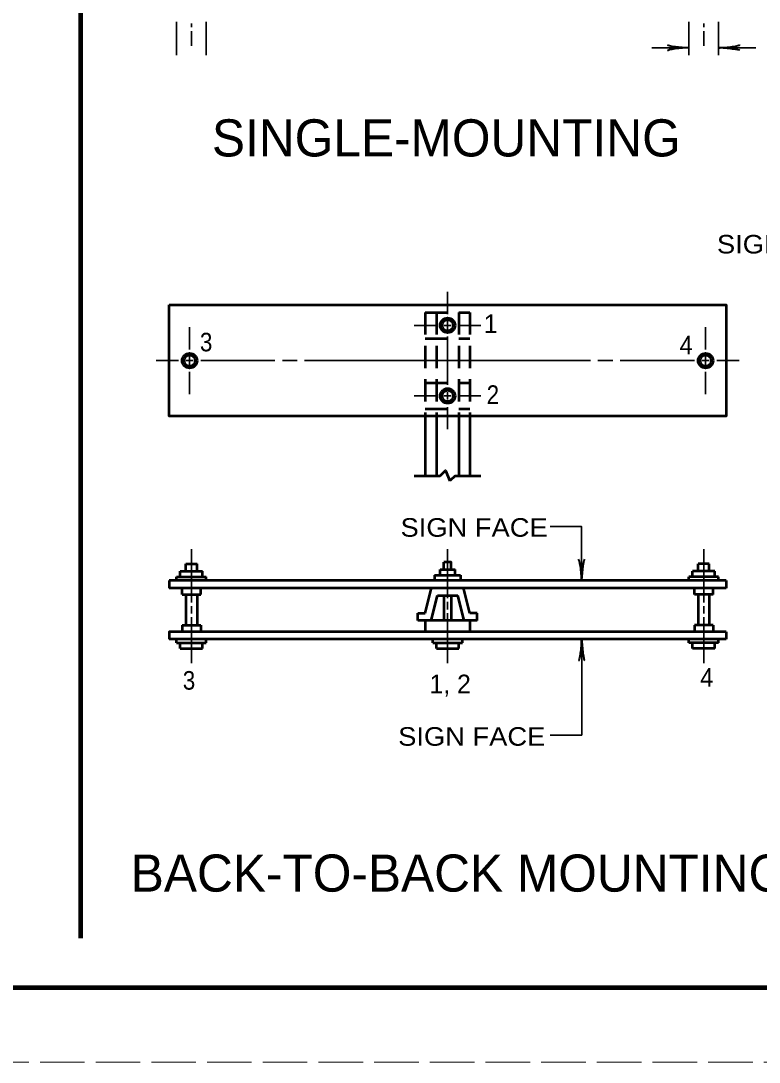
# Model space of a CAD drawing. Extents: x -41 to 639, y -374 to 66.
# Drawn here: x 278.2 to 377.7, y -374.1 to -233.9 of the extents above; entities that cross this region are included whole.
import ezdxf

# ---------------------------------------------------------------- set-up
doc = ezdxf.new("R2010")
doc.units = 0
doc.linetypes.add('LONG_DASHED', pattern=[7.5, 6, -1.5])
doc.linetypes.add('MEDIUM_DASHED', pattern=[4.5, 3, -1.5])
doc.layers.add('1', color=7, linetype='Continuous', lineweight=53)
doc.layers.add('61', color=7, linetype='Continuous', lineweight=35)

msp = doc.modelspace()

# ---------------------------------------------------------------- linework, layer by layer
at = {"layer": '1', "lineweight": 200}
msp.add_line((286.229, -93.651), (286.229, -357.39), dxfattribs=at)
at = {"layer": '1', "lineweight": 35}
for p, q in [((299.192, -238.508), (299.192, -234.008)), ((303.192, -238.508), (303.192, -234.008)), ((368.192, -238.508), (368.192, -234.008)), ((372.192, -238.508), (372.192, -234.008)), ((301.192, -234.758), (301.192, -234.258)), ((301.192, -235.258), (301.192, -237.258)), ((370.192, -234.758), (370.192, -234.258)), ((370.192, -235.258), (370.192, -237.258)), ((363.192, -237.508), (368.192, -237.508)), ((372.192, -237.508), (377.192, -237.508)), ((335.692, -273.386), (335.692, -270.386)), ((335.692, -274.386), (335.692, -275.386)), ((300.942, -278.136), (300.942, -275.136)), ((334.192, -274.886), (331.192, -274.886)), ((336.192, -274.886), (335.192, -274.886)), ((337.192, -274.886), (340.192, -274.886)), ((370.442, -278.136), (370.442, -275.136)), ((335.692, -276.386), (335.692, -279.636)), ((299.442, -279.636), (296.442, -279.636)), ((300.442, -279.636), (301.442, -279.636)), ((300.942, -279.136), (300.942, -280.136)), ((302.442, -279.636), (312.442, -279.636)), ((313.442, -279.636), (315.442, -279.636)), ((316.442, -279.636), (335.692, -279.636)), ((354.942, -279.636), (335.692, -279.636)), ((335.692, -282.886), (335.692, -279.636)), ((357.942, -279.636), (355.942, -279.636)), ((368.942, -279.636), (358.942, -279.636)), ((370.942, -279.636), (369.942, -279.636)), ((370.442, -279.136), (370.442, -280.136)), ((371.942, -279.636), (374.942, -279.636)), ((300.942, -281.136), (300.942, -284.136)), ((370.442, -281.136), (370.442, -284.136)), ((334.192, -284.386), (331.192, -284.386)), ((336.192, -284.386), (335.192, -284.386)), ((335.692, -284.886), (335.692, -283.886)), ((337.192, -284.386), (340.192, -284.386)), ((335.692, -285.886), (335.692, -288.886)), ((301.192, -305.005), (301.192, -312.195)), ((335.692, -311.636), (335.692, -305.005)), ((370.192, -305.005), (370.192, -312.195)), ((335.692, -313.136), (335.692, -312.136)), ((301.192, -312.695), (301.192, -313.695)), ((335.692, -320.386), (335.692, -313.636)), ((370.192, -312.695), (370.192, -313.695)), ((301.192, -314.195), (301.192, -320.386)), ((370.192, -314.195), (370.192, -320.386)), ((353.757, -317.158), (353.757, -330.06)), ((353.757, -330.06), (349.52, -330.06))]:
    msp.add_line(p, q, dxfattribs=at)
at = {"layer": '1', "linetype": 'MEDIUM_DASHED'}
for p, q in [((332.692, -273.136), (338.692, -273.136)), ((332.692, -273.136), (332.692, -287.136)), ((334.192, -273.136), (334.192, -287.136)), ((337.192, -273.136), (337.192, -287.136)), ((338.692, -273.136), (338.692, -287.136)), ((332.692, -276.636), (338.692, -276.636)), ((332.692, -282.636), (338.692, -282.636)), ((332.692, -286.136), (338.692, -286.136))]:
    msp.add_line(p, q, dxfattribs=at)
at = {"layer": '1'}
for p, q in [((332.692, -287.136), (332.692, -295.136)), ((334.192, -287.136), (334.192, -295.136)), ((337.192, -287.136), (337.192, -295.136)), ((338.692, -287.136), (338.692, -295.136)), ((331.192, -295.136), (334.692, -295.136)), ((336.692, -295.136), (335.985, -295.843)), ((336.692, -295.136), (340.192, -295.136)), ((300.442, -308.005), (300.442, -307.005)), ((300.442, -307.005), (301.942, -307.005)), ((301.942, -308.005), (301.942, -307.005)), ((335.192, -307.755), (335.192, -306.755)), ((369.442, -308.005), (369.442, -307.005)), ((370.942, -307.005), (369.442, -307.005)), ((370.942, -308.005), (370.942, -307.005)), ((299.692, -308.755), (299.692, -308.005)), ((299.692, -308.005), (302.692, -308.005)), ((302.692, -308.755), (302.692, -308.005)), ((334.692, -308.505), (334.692, -307.755)), ((334.692, -307.755), (336.692, -307.755)), ((336.692, -308.505), (336.692, -307.755)), ((368.692, -308.755), (368.692, -308.005)), ((371.692, -308.005), (368.692, -308.005)), ((371.692, -308.755), (371.692, -308.005)), ((373.192, -309.255), (298.192, -309.255)), ((298.192, -309.255), (298.192, -310.255)), ((299.192, -308.755), (303.192, -308.755)), ((299.192, -309.255), (299.192, -308.755)), ((303.192, -309.255), (303.192, -308.755)), ((333.942, -308.505), (333.942, -309.255)), ((333.942, -308.505), (337.442, -308.505)), ((337.442, -308.505), (337.442, -309.255)), ((368.192, -309.255), (368.192, -308.755)), ((372.192, -308.755), (368.192, -308.755)), ((372.192, -309.255), (372.192, -308.755)), ((373.192, -309.255), (373.192, -310.255)), ((373.192, -310.255), (298.192, -310.255)), ((299.942, -311.136), (299.942, -310.255)), ((299.942, -311.136), (302.442, -311.136)), ((300.442, -311.136), (300.442, -315.255)), ((301.942, -311.136), (301.942, -315.255)), ((302.442, -311.136), (302.442, -310.255)), ((332.692, -313.636), (333.541, -310.243)), ((333.473, -314.636), (334.321, -311.243)), ((334.321, -311.243), (337.063, -311.243)), ((335.192, -311.243), (335.192, -314.636)), ((336.192, -311.243), (336.192, -314.636)), ((337.911, -314.636), (337.063, -311.243)), ((338.692, -313.636), (337.844, -310.243)), ((368.942, -311.136), (368.942, -310.255)), ((371.442, -311.136), (368.942, -311.136)), ((369.442, -311.136), (369.442, -315.255)), ((370.942, -311.136), (370.942, -315.255)), ((371.442, -311.136), (371.442, -310.255)), ((331.692, -314.636), (331.692, -313.636)), ((331.692, -313.636), (332.692, -313.636)), ((339.692, -313.636), (338.692, -313.636)), ((339.692, -314.636), (339.692, -313.636)), ((299.942, -315.255), (302.442, -315.255)), ((299.942, -315.255), (299.942, -316.136)), ((302.442, -315.255), (302.442, -316.136)), ((339.692, -314.636), (331.692, -314.636)), ((332.692, -314.636), (332.692, -316.136)), ((338.692, -314.636), (338.692, -316.136)), ((371.442, -315.255), (368.942, -315.255)), ((368.942, -315.255), (368.942, -316.136)), ((371.442, -315.255), (371.442, -316.136)), ((373.192, -316.136), (373.192, -317.136)), ((373.192, -317.136), (298.192, -317.136)), ((299.192, -317.636), (299.192, -317.136)), ((299.192, -317.636), (303.192, -317.636)), ((299.692, -318.386), (299.692, -317.636)), ((302.692, -318.386), (302.692, -317.636)), ((303.192, -317.636), (303.192, -317.136)), ((333.692, -317.636), (333.692, -317.136)), ((333.692, -317.636), (337.692, -317.636)), ((334.192, -318.386), (334.192, -317.636)), ((337.192, -318.386), (337.192, -317.636)), ((337.692, -317.636), (337.692, -317.136)), ((368.192, -317.636), (368.192, -317.136)), ((372.192, -317.636), (368.192, -317.636)), ((368.692, -318.386), (368.692, -317.636)), ((371.692, -318.386), (371.692, -317.636)), ((372.192, -317.636), (372.192, -317.136)), ((299.692, -318.386), (302.692, -318.386)), ((334.192, -318.386), (337.192, -318.386)), ((371.692, -318.386), (368.692, -318.386))]:
    msp.add_line(p, q, dxfattribs=at)
msp.add_lwpolyline([(298.192, -272.136), (373.192, -272.136), (373.192, -287.136), (298.192, -287.136)], close=True, dxfattribs=at)
for points in [[(334.692, -295.136), (335.399, -294.429), (335.985, -295.843)], [(336.192, -307.755), (336.192, -306.755), (335.192, -306.755)], [(373.192, -316.136), (298.192, -316.136), (298.192, -317.136)]]:
    msp.add_lwpolyline(points, dxfattribs=at)
at = {"layer": '1', "lineweight": 35}
msp.add_lwpolyline([(353.737, -309.255), (353.737, -301.985), (349.5, -301.985)], dxfattribs=at)
at = {"layer": '1'}
for centre, radius in [((335.692, -274.886), 1), ((335.692, -274.886), 0.75), ((300.942, -279.636), 1), ((300.942, -279.636), 0.75), ((370.442, -279.636), 1), ((370.442, -279.636), 0.75), ((335.692, -284.386), 1), ((335.692, -284.386), 0.75)]:
    msp.add_circle(centre, radius, dxfattribs=at)
at = {"layer": '1', "lineweight": 40}
for centre, major_axis, ratio, start_param, end_param in [((367.101, -237.784), (1.786, 0.156), 0.122415, 0.8963533, 3.1415927), ((367.072, -237.296), (1.756, -0.176), 0.07063, 3.1407148, 5.41811), ((373.283, -237.232), (-1.786, -0.156), 0.122415, 0.8963533, 3.1415927), ((373.283, -237.232), (-1.786, -0.156), 0.122415, 0.8963533, 3.1415927), ((373.283, -237.232), (-1.786, -0.156), 0.122415, 0.8963533, 3.1415927), ((373.313, -237.719), (-1.756, 0.176), 0.07063, 3.1407148, 5.41811), ((373.313, -237.719), (-1.756, 0.176), 0.07063, 3.1407148, 5.41811), ((373.313, -237.719), (-1.756, 0.176), 0.07063, 3.1407148, 5.41811), ((353.461, -308.164), (0.156, -1.786), 0.122415, 0.8963533, 3.1415927), ((353.949, -308.134), (-0.176, -1.756), 0.07063, 3.1407148, 5.41811), ((353.481, -318.25), (0.156, 1.786), 0.122415, 3.1415927, 5.386832), ((353.969, -318.279), (-0.176, 1.756), 0.07063, 0.8650754, 3.1424706)]:
    msp.add_ellipse(centre, major_axis=major_axis, ratio=ratio, start_param=start_param, end_param=end_param, dxfattribs=at)
at = {"layer": '61', "lineweight": 158}
msp.add_line((628.362, -364.098), (-10.698, -364.078), dxfattribs=at)
at = {"layer": '61', "linetype": 'LONG_DASHED', "lineweight": 13}
msp.add_line((639.302, -374.078), (-40.758, -374.098), dxfattribs=at)

# ---------------------------------------------------------------- texts
at = {"layer": '1'}
for s, height, p in [('SINGLE-MOUNTING', 5, (303.947, -252.146)), ('1', 2.5, (340.561, -275.924)), ('1, 2', 2.5, (333.25, -324.416)), ('BACK-TO-BACK MOUNTING', 5, (293.019, -351.137))]:
    msp.add_text(s, height=height, dxfattribs=at).set_placement(p)
for s, width, p in [('SIGN FACE', 1.1, (371.971, -265.21)), ('3', 0.9, (302.337, -278.388)), ('4', 0.95, (366.945, -278.786)), ('2', 0.9, (340.959, -285.463)), ('SIGN FACE', 1.1, (329.356, -303.35)), ('4', 0.95, (369.727, -323.542)), ('3', 0.9, (300.032, -323.939)), ('SIGN FACE', 1.1, (329.038, -331.491))]:
    msp.add_text(s, height=2.5, dxfattribs=dict(at, width=width)).set_placement(p)

doc.saveas('drawing.dxf')
